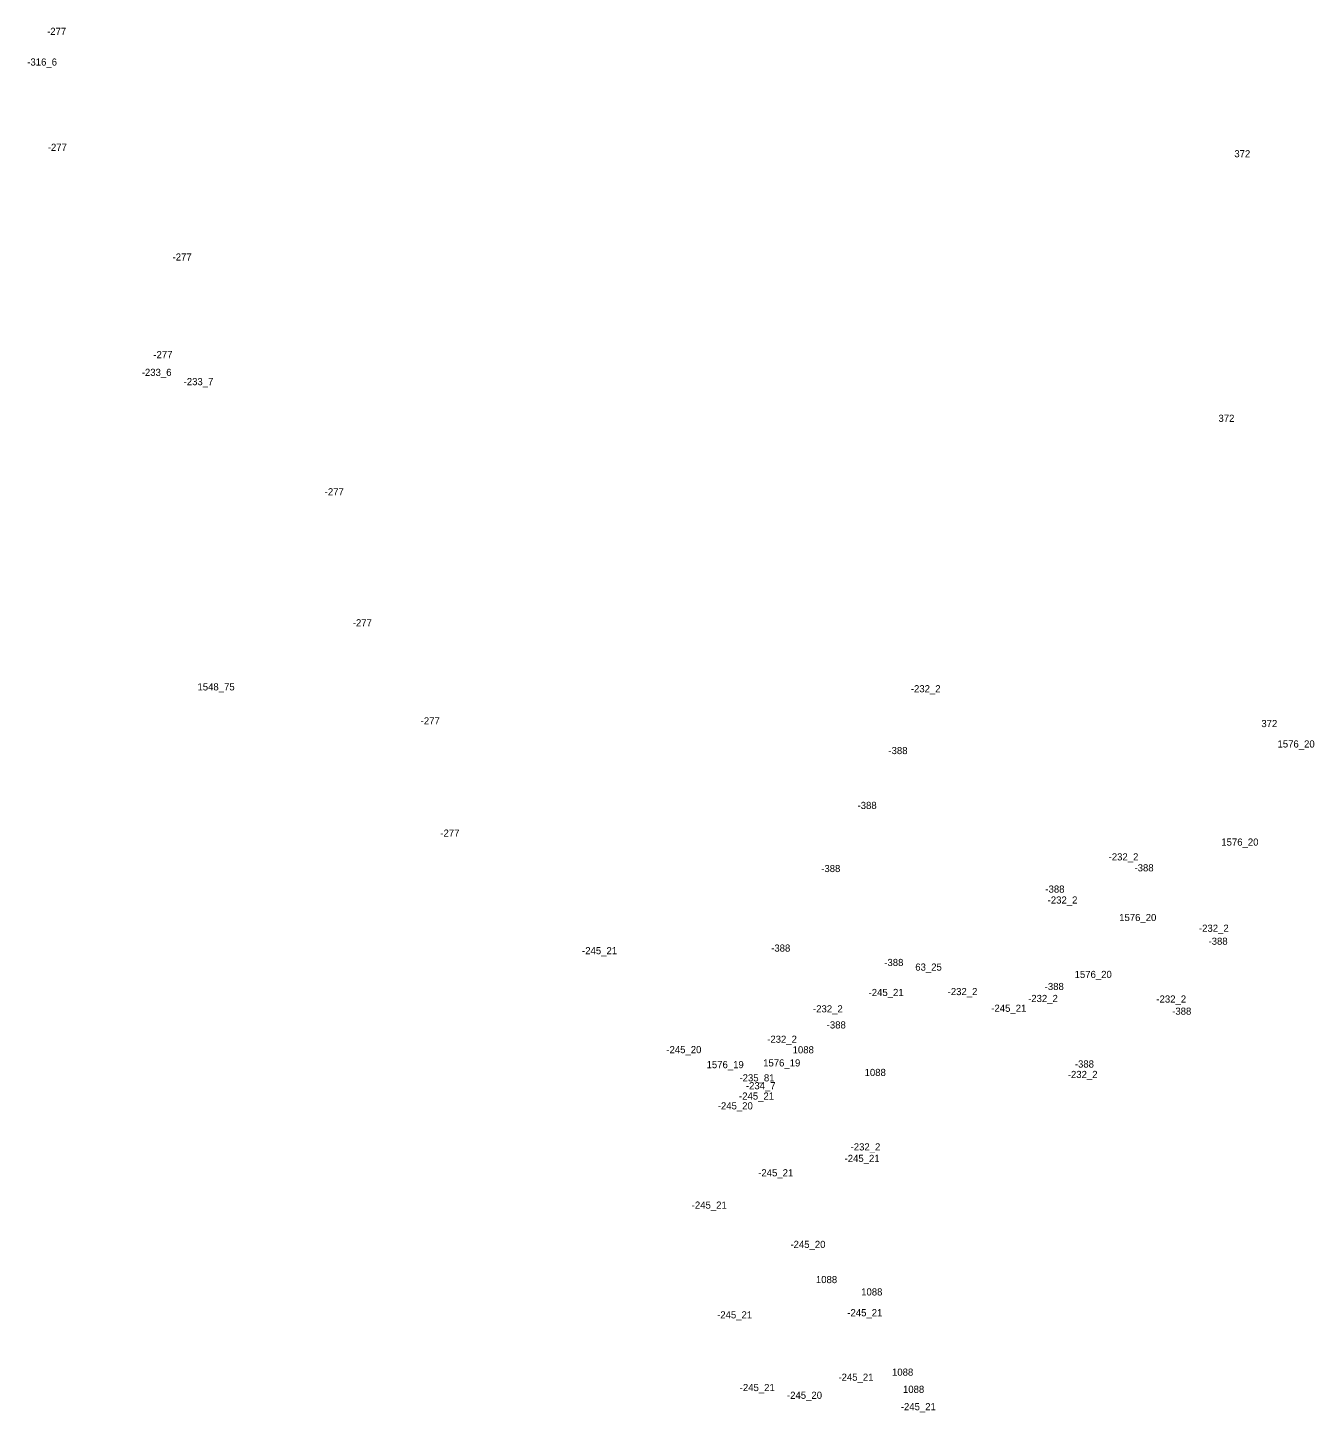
# Model space of a CAD drawing. Extents: x -660434 to -656144, y -997850 to -994016.
# Drawn here: x -657619 to -656898, y -997850 to -997074 of the extents above; entities that cross this region are included whole.
import ezdxf
from ezdxf.enums import TextEntityAlignment as Align

# ---------------------------------------------------------------- set-up
doc = ezdxf.new("R2010")
doc.units = 0
doc.header["$LTSCALE"] = 1.6
doc.layers.add('24', color=7, linetype='Continuous')

msp = doc.modelspace()

# ---------------------------------------------------------------- texts
at = {"layer": '24'}
for s, p in [('-277', (-657602.725, -997078.53)), ('-316_6', (-657610.857, -997095.69)), ('-277', (-657602.335, -997143.45)), ('372', (-656938.503, -997147.06)), ('-277', (-657532.445, -997204.92)), ('-277', (-657543.195, -997259.58)), ('-233_6', (-657546.708, -997269.52)), ('-233_7', (-657523.268, -997274.7)), ('372', (-656947.403, -997295.24)), ('-277', (-657447.195, -997336.41)), ('-277', (-657431.455, -997409.78)), ('1548_75', (-657513.417, -997445.67)), ('-232_2', (-657115.872, -997446.73)), ('-277', (-657393.435, -997464.73)), ('372', (-656923.373, -997466.21)), ('-388', (-657131.415, -997481.34)), ('1576_20', (-656908.373, -997477.65)), ('-388', (-657148.695, -997512.07)), ('-277', (-657382.415, -997527.58)), ('1576_20', (-656939.863, -997532.59)), ('-232_2', (-657005.062, -997540.88)), ('-388', (-657169.045, -997547.42)), ('-388', (-656993.555, -997547.03)), ('-388', (-657043.475, -997558.94)), ('-232_2', (-657039.222, -997565.06)), ('1576_20', (-656997.083, -997574.85)), ('-232_2', (-656954.462, -997580.86)), ('-388', (-657197.085, -997591.98)), ('-388', (-656952.085, -997588.14)), ('-245_21', (-657298.569, -997593.42)), ('-388', (-657133.715, -997600.04)), ('63_25', (-657114.28, -997602.62)), ('1576_20', (-657022.043, -997606.73)), ('-388', (-657043.855, -997613.49)), ('-245_21', (-657138.049, -997616.85)), ('-232_2', (-657095.242, -997616.33)), ('-232_2', (-657050.182, -997620.2)), ('-232_2', (-656978.312, -997620.52)), ('-232_2', (-657170.662, -997626)), ('-245_21', (-657069.319, -997625.68)), ('-388', (-656972.435, -997627.32)), ('-388', (-657165.975, -997635)), ('-232_2', (-657196.352, -997643.03)), ('-245_20', (-657251.34, -997648.85)), ('1088', (-657184.474, -997648.95)), ('1576_19', (-657228.207, -997657.25)), ('1576_19', (-657196.527, -997656.29)), ('1088', (-657144.154, -997661.63)), ('-388', (-657026.965, -997656.9)), ('-235_81', (-657210.385, -997664.66)), ('-234_7', (-657208.282, -997669.07)), ('-232_2', (-657027.942, -997662.76)), ('-245_21', (-657210.629, -997674.86)), ('-245_20', (-657222.54, -997680.34)), ('-232_2', (-657149.622, -997703.32)), ('-245_21', (-657151.499, -997709.78)), ('-245_21', (-657199.879, -997717.84)), ('-245_21', (-657237.129, -997735.94)), ('-245_20', (-657181.84, -997757.94)), ('1088', (-657171.424, -997777.64)), ('1088', (-657146.074, -997784.56)), ('-245_21', (-657222.919, -997797.4)), ('-245_21', (-657149.959, -997796.21)), ('-245_21', (-657154.949, -997832.32)), ('1088', (-657128.794, -997829.5)), ('-245_21', (-657210.249, -997838.12)), ('1088', (-657122.654, -997839.11)), ('-245_20', (-657183.76, -997842.45)), ('-245_21', (-657120.009, -997848.84))]:
    msp.add_text(s, height=4, dxfattribs=at).set_placement(p, align=Align.CENTER)

doc.saveas('drawing.dxf')
